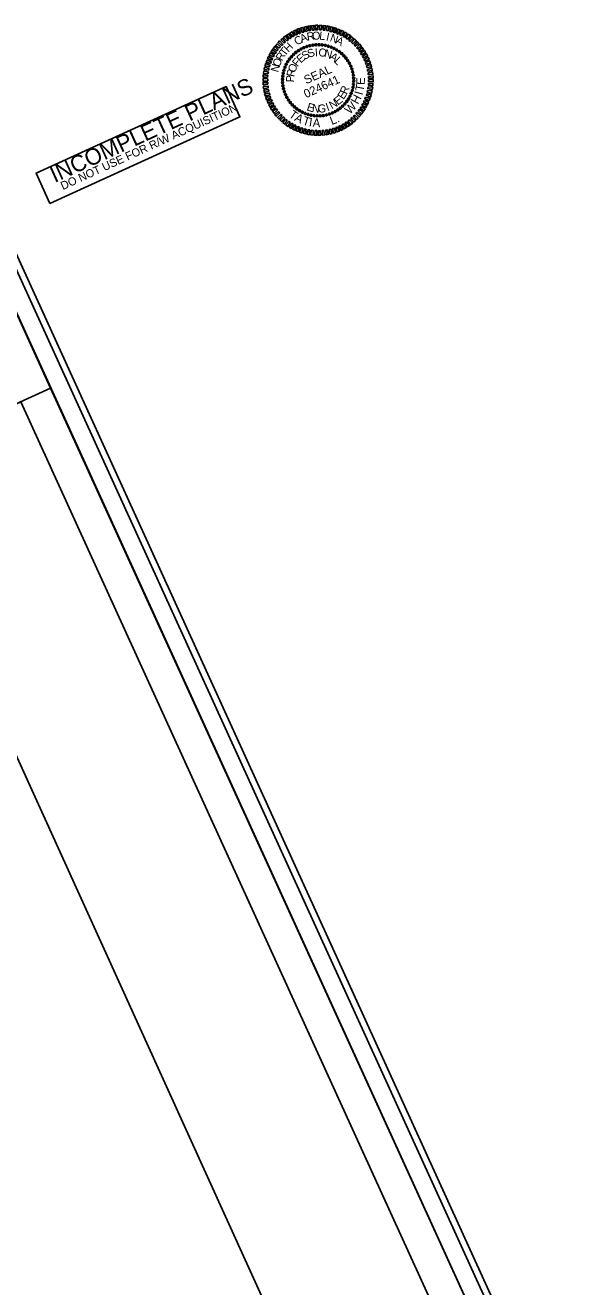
# Model space of a CAD drawing. Extents: x 2247910 to 2249896, y 662531 to 664261.
# Drawn here: x 2249505 to 2249896, y 663373 to 664261 of the extents above; entities that cross this region are included whole.
import ezdxf

# ---------------------------------------------------------------- set-up
doc = ezdxf.new("R2010")
doc.units = 0
for name, color, linetype in [('Sheet Clip Boundary CELL', 7, 'Continuous'), ('Sheet Layout Plan Border', 7, 'Continuous'), ('Sheet Plan CELL', 7, 'Continuous'), ('Sheet Plan Layout CELL', 7, 'Continuous'), ('Sheet Plot Border Inside CELL', 7, 'Continuous'), ('Sheet Plot Border Outside CELL', 7, 'Continuous'), ('Sheet Professional Seal CELL', 7, 'Continuous'), ('Sheet Sticker Incomplete CELL', 7, 'Continuous')]:
    doc.layers.add(name, color=color, linetype=linetype)

msp = doc.modelspace()

# ---------------------------------------------------------------- linework, layer by layer
at = {"layer": 'Sheet Clip Boundary CELL'}
msp.add_lwpolyline([(2248241.67, 663371.06), (2248514.44, 662770.57), (2248551.22, 662641.58), (2249825.2, 663222.11), (2249780.68, 663312.06), (2249743.43, 663294.89), (2249677.44, 663353.62), (2249425.27, 663908.72), (2249477.5, 663985.14), (2249305.27, 663906.66), (2249217.58, 664099.11), (2248115.83, 663597.06)], close=True, dxfattribs=at)
at = {"layer": 'Sheet Layout Plan Border'}
msp.add_lwpolyline([(2248198.13, 663481.51), (2248575.77, 662652.77), (2249849.75, 663233.3), (2249502.05, 663996.33), (2249329.83, 663917.85), (2249242.13, 664110.3), (2248140.38, 663608.25)], close=True, dxfattribs=at)
at = {"layer": 'Sheet Plan CELL'}
for points in [[(2249435.32, 664198.33), (2248070.33, 663576.33), (2248505.72, 662620.85), (2249870.7, 663242.85)], [(2248505.72, 662620.85), (2248070.31, 663576.29), (2249253.26, 664115.38), (2249268.84, 664081.19), (2249359.88, 664122.68), (2249406.53, 664020.29), (2249497.53, 664061.77), (2249870.7, 663242.85)]]:
    msp.add_lwpolyline(points, close=True, dxfattribs=at)
at = {"layer": 'Sheet Plan Layout CELL'}
for points in [[(2249305.27, 663906.66), (2249523.01, 664005.88), (2249435.34, 664198.34), (2249217.58, 664099.11)], [(2248070.31, 663576.29), (2248505.72, 662620.85), (2249870.68, 663242.84), (2249522.99, 664005.87), (2249305.27, 663906.66), (2249217.58, 664099.11)]]:
    msp.add_lwpolyline(points, close=True, dxfattribs=at)
at = {"layer": 'Sheet Plot Border Inside CELL'}
msp.add_lwpolyline([(2248367.09, 662554.92), (2249883.1, 663245.75), (2249445.65, 664205.77), (2247929.62, 663514.94)], close=True, dxfattribs=at)
at = {"layer": 'Sheet Plot Border Outside CELL'}
msp.add_lwpolyline([(2248363.56, 662531.33), (2249895.5, 663229.41), (2249441.45, 664225.83), (2247909.5, 663527.75)], close=True, dxfattribs=at)
at = {"layer": 'Sheet Professional Seal CELL'}
for p, q in [((2249705.47, 664247.08), (2249705.47, 664247.08)), ((2249707.57, 664247.54), (2249707.57, 664247.54)), ((2249709.77, 664247.78), (2249709.77, 664247.78)), ((2249711.97, 664247.79), (2249711.97, 664247.79)), ((2249714.16, 664247.69), (2249714.16, 664247.69)), ((2249716.31, 664247.29), (2249716.31, 664247.29)), ((2249692.51, 664239.35), (2249692.51, 664239.35)), ((2249694, 664240.91), (2249694, 664240.91)), ((2249695.66, 664242.33), (2249695.66, 664242.33)), ((2249697.5, 664243.61), (2249697.5, 664243.61)), ((2249699.33, 664244.77), (2249699.33, 664244.77)), ((2249701.31, 664245.73), (2249701.31, 664245.73)), ((2249703.37, 664246.51), (2249703.37, 664246.51)), ((2249718.46, 664246.79), (2249718.46, 664246.79)), ((2249720.5, 664246.07), (2249720.5, 664246.07)), ((2249722.55, 664245.19), (2249722.55, 664245.19)), ((2249724.41, 664244.12), (2249724.41, 664244.12)), ((2249726.24, 664242.87), (2249726.24, 664242.87)), ((2249727.96, 664241.51), (2249727.96, 664241.51)), ((2249729.52, 664240.02), (2249729.52, 664240.02)), ((2249730.94, 664238.36), (2249730.94, 664238.36)), ((2249687.23, 664229.86), (2249687.23, 664229.86)), ((2249687.95, 664231.89), (2249687.95, 664231.89)), ((2249688.83, 664233.94), (2249688.83, 664233.94)), ((2249689.9, 664235.8), (2249689.9, 664235.8)), ((2249691.15, 664237.64), (2249691.15, 664237.64)), ((2249732.21, 664236.52), (2249732.21, 664236.52)), ((2249733.38, 664234.69), (2249733.38, 664234.69)), ((2249734.34, 664232.71), (2249734.34, 664232.71)), ((2249735.11, 664230.64), (2249735.11, 664230.64)), ((2249686.23, 664223.36), (2249686.23, 664223.36)), ((2249686.24, 664221.16), (2249686.24, 664221.16)), ((2249686.33, 664225.55), (2249686.33, 664225.55)), ((2249686.72, 664227.7), (2249686.72, 664227.7)), ((2249711.31, 664222.7), (2249711.31, 664222.7)), ((2249735.69, 664228.54), (2249735.69, 664228.54)), ((2249736.15, 664226.45), (2249736.15, 664226.45)), ((2249736.38, 664224.24), (2249736.38, 664224.24)), ((2249736.39, 664222.05), (2249736.39, 664222.05)), ((2249686.48, 664218.96), (2249686.48, 664218.96)), ((2249686.94, 664216.87), (2249686.94, 664216.87)), ((2249687.51, 664214.76), (2249687.51, 664214.76)), ((2249688.29, 664212.7), (2249688.29, 664212.7)), ((2249733.8, 664211.47), (2249733.8, 664211.47)), ((2249734.68, 664213.52), (2249734.68, 664213.52)), ((2249735.4, 664215.55), (2249735.4, 664215.55)), ((2249735.9, 664217.71), (2249735.9, 664217.71)), ((2249736.29, 664219.86), (2249736.29, 664219.86)), ((2249689.25, 664210.72), (2249689.25, 664210.72)), ((2249690.41, 664208.89), (2249690.41, 664208.89)), ((2249691.69, 664207.05), (2249691.69, 664207.05)), ((2249693.11, 664205.39), (2249693.11, 664205.39)), ((2249694.66, 664203.9), (2249694.66, 664203.9)), ((2249726.97, 664203.08), (2249726.97, 664203.08)), ((2249728.63, 664204.5), (2249728.63, 664204.5)), ((2249730.12, 664206.05), (2249730.12, 664206.05)), ((2249731.48, 664207.77), (2249731.48, 664207.77)), ((2249732.73, 664209.61), (2249732.73, 664209.61)), ((2249696.38, 664202.54), (2249696.38, 664202.54)), ((2249698.22, 664201.29), (2249698.22, 664201.29)), ((2249700.08, 664200.22), (2249700.08, 664200.22)), ((2249702.13, 664199.34), (2249702.13, 664199.34)), ((2249704.16, 664198.62), (2249704.16, 664198.62)), ((2249706.31, 664198.11), (2249706.31, 664198.11)), ((2249708.47, 664197.72), (2249708.47, 664197.72)), ((2249710.66, 664197.62), (2249710.66, 664197.62)), ((2249712.85, 664197.63), (2249712.85, 664197.63)), ((2249715.05, 664197.87), (2249715.05, 664197.87)), ((2249717.15, 664198.33), (2249717.15, 664198.33)), ((2249719.25, 664198.9), (2249719.25, 664198.9)), ((2249721.32, 664199.68), (2249721.32, 664199.68)), ((2249723.3, 664200.64), (2249723.3, 664200.64)), ((2249725.13, 664201.8), (2249725.13, 664201.8))]:
    msp.add_line(p, q, dxfattribs=at)
for points in [[(2249693.3, 664253.29), (2249691.47, 664255.97), (2249692.94, 664256.86), (2249694.33, 664253.92)], [(2249695.47, 664254.55), (2249693.9, 664257.41), (2249695.42, 664258.05), (2249696.58, 664255.01)], [(2249697.68, 664255.5), (2249696.33, 664258.46), (2249697.85, 664259.1), (2249698.79, 664255.96)], [(2249700.01, 664256.4), (2249698.85, 664259.44), (2249700.47, 664259.86), (2249701.19, 664256.72)], [(2249702.36, 664257.04), (2249701.45, 664260.13), (2249703.05, 664260.59), (2249703.52, 664257.4)], [(2249704.91, 664257.59), (2249704.02, 664260.76), (2249705.73, 664261.1), (2249705.97, 664257.8)], [(2249707.36, 664258), (2249706.76, 664261.13), (2249708.38, 664261.32), (2249708.47, 664258.11)], [(2249709.79, 664258.11), (2249709.53, 664261.46), (2249711.05, 664261.49), (2249710.98, 664258.27)], [(2249712.23, 664258.18), (2249712.14, 664261.38), (2249713.84, 664261.39), (2249713.46, 664258.14)], [(2249714.8, 664258.09), (2249714.84, 664261.24), (2249716.56, 664261.09), (2249715.91, 664257.94)], [(2249717.13, 664257.67), (2249717.52, 664261.03), (2249719.14, 664260.62), (2249718.38, 664257.58)], [(2249719.62, 664257.16), (2249720.16, 664260.43), (2249721.8, 664259.96), (2249720.77, 664256.91)], [(2249721.99, 664256.53), (2249722.78, 664259.75), (2249724.37, 664259.16), (2249723.17, 664256.25)], [(2249724.35, 664255.69), (2249725.34, 664258.72), (2249726.93, 664258.12), (2249725.37, 664255.27)], [(2249726.69, 664254.78), (2249727.85, 664257.78), (2249729.37, 664256.98), (2249727.75, 664254.16)], [(2249728.87, 664253.62), (2249730.23, 664256.55), (2249731.69, 664255.63), (2249729.81, 664253.01)], [(2249683.91, 664245.32), (2249681.29, 664247.21), (2249682.41, 664248.49), (2249684.72, 664246.19)], [(2249685.48, 664247.19), (2249683.09, 664249.29), (2249684.21, 664250.46), (2249686.49, 664247.98)], [(2249687.37, 664248.94), (2249685.08, 664251.19), (2249686.31, 664252.24), (2249688.18, 664249.69)], [(2249689.29, 664250.52), (2249687.02, 664252.95), (2249688.43, 664253.98), (2249690.14, 664251.19)], [(2249691.24, 664252.02), (2249689.19, 664254.6), (2249690.63, 664255.42), (2249692.27, 664252.65)], [(2249730.9, 664252.3), (2249732.52, 664255.13), (2249734.01, 664254.16), (2249731.95, 664251.68)], [(2249733, 664250.84), (2249734.82, 664253.59), (2249736.05, 664252.45), (2249733.94, 664250.22)], [(2249734.8, 664249.29), (2249736.86, 664251.88), (2249738.12, 664250.7), (2249735.71, 664248.5)], [(2249736.59, 664247.53), (2249738.83, 664249.98), (2249739.97, 664248.8), (2249737.48, 664246.78)], [(2249738.32, 664245.68), (2249740.75, 664248.05), (2249741.71, 664246.68), (2249739.07, 664244.87)], [(2249678.68, 664236.9), (2249675.77, 664237.99), (2249676.36, 664239.58), (2249679.26, 664237.93)], [(2249679.86, 664239.14), (2249676.91, 664240.43), (2249677.7, 664241.94), (2249680.46, 664240.12)], [(2249680.97, 664241.29), (2249678.23, 664242.84), (2249679.02, 664244.25), (2249681.72, 664242.29)], [(2249682.45, 664243.34), (2249679.65, 664245.03), (2249680.73, 664246.4), (2249683.07, 664244.28)], [(2249739.86, 664243.74), (2249742.33, 664245.91), (2249743.31, 664244.49), (2249740.57, 664242.91)], [(2249741.26, 664241.75), (2249743.93, 664243.73), (2249744.77, 664242.25), (2249741.94, 664240.74)], [(2249742.53, 664239.69), (2249745.32, 664241.4), (2249746.12, 664239.89), (2249743.12, 664238.64)], [(2249743.61, 664237.43), (2249746.51, 664238.92), (2249747.21, 664237.37), (2249744.11, 664236.34)], [(2249675.99, 664227.37), (2249672.82, 664227.57), (2249673.15, 664229.26), (2249676.35, 664228.52)], [(2249676.53, 664229.81), (2249673.37, 664230.24), (2249673.63, 664231.95), (2249676.73, 664230.95)], [(2249677.11, 664232.16), (2249673.93, 664232.86), (2249674.39, 664234.5), (2249677.37, 664233.27)], [(2249677.91, 664234.62), (2249674.74, 664235.43), (2249675.4, 664236.99), (2249678.31, 664235.68)], [(2249744.61, 664235.14), (2249747.6, 664236.4), (2249748.2, 664234.85), (2249745.01, 664234)], [(2249745.37, 664232.85), (2249748.41, 664233.9), (2249748.93, 664232.28), (2249745.64, 664231.65)], [(2249746.07, 664230.36), (2249749.05, 664231.29), (2249749.44, 664229.59), (2249746.14, 664229.24)], [(2249675.84, 664222.41), (2249672.54, 664222.17), (2249672.58, 664223.89), (2249675.84, 664223.62)], [(2249675.84, 664219.99), (2249672.65, 664219.53), (2249672.6, 664221.21), (2249675.91, 664221.18)], [(2249675.79, 664224.92), (2249672.68, 664224.87), (2249672.72, 664226.59), (2249675.95, 664226.03)], [(2249746.47, 664227.91), (2249749.56, 664228.61), (2249749.93, 664226.96), (2249746.54, 664226.79)], [(2249746.83, 664220.49), (2249749.94, 664220.54), (2249749.91, 664218.82), (2249746.68, 664219.38)], [(2249746.79, 664225.42), (2249749.98, 664225.88), (2249750.03, 664224.2), (2249746.72, 664224.23)], [(2249746.79, 664223), (2249750.09, 664223.24), (2249750.05, 664221.52), (2249746.79, 664221.79)], [(2249676.15, 664217.5), (2249673.06, 664216.8), (2249672.7, 664218.45), (2249676.08, 664218.62)], [(2249676.56, 664215.05), (2249673.57, 664214.12), (2249673.19, 664215.81), (2249676.49, 664216.17)], [(2249677.25, 664212.56), (2249674.22, 664211.5), (2249673.69, 664213.13), (2249676.98, 664213.75)], [(2249745.52, 664213.24), (2249748.7, 664212.55), (2249748.23, 664210.91), (2249745.26, 664212.14)], [(2249746.1, 664215.6), (2249749.26, 664215.17), (2249749, 664213.46), (2249745.9, 664214.46)], [(2249746.63, 664218.04), (2249749.8, 664217.83), (2249749.47, 664216.15), (2249746.28, 664216.89)], [(2249678.02, 664210.27), (2249675.02, 664209.01), (2249674.43, 664210.56), (2249677.61, 664211.4)], [(2249679.01, 664207.98), (2249676.12, 664206.49), (2249675.41, 664208.04), (2249678.51, 664209.07)], [(2249680.1, 664205.72), (2249677.3, 664204.01), (2249676.51, 664205.52), (2249679.51, 664206.77)], [(2249681.36, 664203.66), (2249678.7, 664201.68), (2249677.86, 664203.16), (2249680.68, 664204.67)], [(2249741.66, 664204.12), (2249744.4, 664202.57), (2249743.61, 664201.16), (2249740.91, 664203.12)], [(2249742.77, 664206.27), (2249745.72, 664204.98), (2249744.92, 664203.47), (2249742.17, 664205.29)], [(2249743.94, 664208.51), (2249746.86, 664207.42), (2249746.26, 664205.83), (2249743.37, 664207.48)], [(2249744.72, 664210.79), (2249747.89, 664209.98), (2249747.23, 664208.42), (2249744.32, 664209.73)], [(2249682.77, 664201.67), (2249680.3, 664199.49), (2249679.32, 664200.92), (2249682.06, 664202.5)], [(2249684.31, 664199.73), (2249681.88, 664197.36), (2249680.92, 664198.73), (2249683.56, 664200.54)], [(2249686.03, 664197.88), (2249683.8, 664195.43), (2249682.66, 664196.61), (2249685.14, 664198.63)], [(2249687.83, 664196.11), (2249685.77, 664193.53), (2249684.51, 664194.71), (2249686.92, 664196.91)], [(2249689.63, 664194.57), (2249687.81, 664191.82), (2249686.57, 664192.96), (2249688.69, 664195.19)], [(2249691.73, 664193.11), (2249690.1, 664190.28), (2249688.62, 664191.25), (2249690.67, 664193.73)], [(2249733.34, 664194.89), (2249735.6, 664192.46), (2249734.2, 664191.43), (2249732.49, 664194.22)], [(2249735.25, 664196.47), (2249737.55, 664194.22), (2249736.32, 664193.17), (2249734.44, 664195.72)], [(2249737.15, 664198.22), (2249739.54, 664196.12), (2249738.42, 664194.95), (2249736.14, 664197.43)], [(2249738.72, 664200.09), (2249741.34, 664198.2), (2249740.22, 664196.92), (2249737.9, 664199.22)], [(2249740.18, 664202.07), (2249742.98, 664200.38), (2249741.9, 664199.01), (2249739.56, 664201.13)], [(2249693.76, 664191.78), (2249692.4, 664188.86), (2249690.94, 664189.78), (2249692.82, 664192.4)], [(2249695.93, 664190.63), (2249694.77, 664187.63), (2249693.26, 664188.42), (2249694.88, 664191.25)], [(2249698.27, 664189.72), (2249697.29, 664186.69), (2249695.7, 664187.29), (2249697.26, 664190.14)], [(2249700.64, 664188.88), (2249699.85, 664185.66), (2249698.26, 664186.25), (2249699.46, 664189.16)], [(2249703.01, 664188.25), (2249702.47, 664184.98), (2249700.83, 664185.45), (2249701.85, 664188.5)], [(2249705.5, 664187.74), (2249705.11, 664184.37), (2249703.49, 664184.79), (2249704.25, 664187.83)], [(2249707.83, 664187.32), (2249707.78, 664184.17), (2249706.07, 664184.32), (2249706.72, 664187.47)], [(2249710.4, 664187.23), (2249710.49, 664184.03), (2249708.79, 664184.02), (2249709.17, 664187.27)], [(2249712.84, 664187.3), (2249713.1, 664183.95), (2249711.58, 664183.92), (2249711.65, 664187.14)], [(2249715.26, 664187.41), (2249715.87, 664184.28), (2249714.25, 664184.09), (2249714.16, 664187.29)], [(2249717.72, 664187.82), (2249718.61, 664184.65), (2249716.9, 664184.31), (2249716.66, 664187.61)], [(2249720.26, 664188.37), (2249721.18, 664185.28), (2249719.58, 664184.82), (2249719.11, 664188.01)], [(2249722.61, 664189.01), (2249723.78, 664185.97), (2249722.15, 664185.55), (2249721.44, 664188.69)], [(2249724.95, 664189.91), (2249726.3, 664186.95), (2249724.78, 664186.31), (2249723.84, 664189.45)], [(2249727.15, 664190.86), (2249728.73, 664188), (2249727.21, 664187.36), (2249726.04, 664190.4)], [(2249729.33, 664192.12), (2249731.15, 664189.44), (2249729.69, 664188.55), (2249728.3, 664191.49)], [(2249731.38, 664193.39), (2249733.44, 664190.81), (2249732, 664189.99), (2249730.36, 664192.76)]]:
    msp.add_lwpolyline(points, close=True, dxfattribs=at)
for centre, major_axis in [((2249703.35, 664246.49), (-0.229, 0.683)), ((2249705.45, 664247.09), (-0.168, 0.7)), ((2249707.6, 664247.51), (-0.107, 0.712)), ((2249709.78, 664247.74), (-0.044, 0.719)), ((2249711.96, 664247.78), (0.019, 0.72)), ((2249714.15, 664247.62), (0.081, 0.715)), ((2249716.31, 664247.28), (0.143, 0.706)), ((2249718.43, 664246.75), (0.204, 0.69)), ((2249691.15, 664237.62), (-0.579, 0.428)), ((2249692.53, 664239.32), (-0.539, 0.477)), ((2249694.05, 664240.89), (-0.496, 0.522)), ((2249695.7, 664242.33), (-0.448, 0.563)), ((2249697.47, 664243.62), (-0.398, 0.6)), ((2249699.34, 664244.74), (-0.344, 0.633)), ((2249701.31, 664245.7), (-0.287, 0.66)), ((2249720.5, 664246.04), (0.264, 0.67)), ((2249722.5, 664245.15), (0.321, 0.644)), ((2249724.41, 664244.09), (0.376, 0.614)), ((2249726.23, 664242.87), (0.428, 0.579)), ((2249727.93, 664241.49), (0.477, 0.539)), ((2249729.5, 664239.97), (0.522, 0.496)), ((2249730.94, 664238.32), (0.563, 0.448)), ((2249687.26, 664229.82), (-0.69, 0.204)), ((2249687.98, 664231.89), (-0.67, 0.264)), ((2249688.87, 664233.89), (-0.644, 0.321)), ((2249689.93, 664235.8), (-0.614, 0.376)), ((2249732.22, 664236.55), (0.6, 0.398)), ((2249733.35, 664234.68), (0.633, 0.344)), ((2249734.31, 664232.71), (0.66, 0.287)), ((2249735.1, 664230.67), (0.683, 0.229)), ((2249735.7, 664228.56), (0.7, 0.168)), ((2249686.24, 664223.36), (-0.72, 0.019)), ((2249686.28, 664221.17), (-0.719, -0.044)), ((2249686.39, 664225.54), (-0.715, 0.081)), ((2249686.74, 664227.7), (-0.706, 0.143)), ((2249736.12, 664226.42), (0.712, 0.107)), ((2249736.23, 664219.87), (0.715, -0.081)), ((2249736.35, 664224.24), (0.719, 0.044)), ((2249736.38, 664222.05), (0.72, -0.019)), ((2249686.51, 664218.99), (-0.712, -0.107)), ((2249686.93, 664216.84), (-0.7, -0.168)), ((2249687.53, 664214.74), (-0.683, -0.229)), ((2249688.32, 664212.7), (-0.66, -0.287)), ((2249689.28, 664210.73), (-0.633, -0.344)), ((2249733.76, 664211.52), (0.644, -0.321)), ((2249734.65, 664213.52), (0.67, -0.264)), ((2249735.36, 664215.59), (0.69, -0.204)), ((2249735.89, 664217.71), (0.706, -0.143)), ((2249690.4, 664208.86), (-0.6, -0.398)), ((2249691.69, 664207.09), (-0.563, -0.448)), ((2249693.12, 664205.44), (-0.522, -0.496)), ((2249694.7, 664203.92), (-0.477, -0.539)), ((2249696.4, 664202.54), (-0.428, -0.579)), ((2249725.16, 664201.79), (0.398, -0.6)), ((2249726.93, 664203.08), (0.448, -0.563)), ((2249728.58, 664204.52), (0.496, -0.522)), ((2249730.1, 664206.09), (0.539, -0.477)), ((2249731.48, 664207.79), (0.579, -0.428)), ((2249732.7, 664209.6), (0.614, -0.376)), ((2249698.21, 664201.32), (-0.376, -0.614)), ((2249700.13, 664200.26), (-0.321, -0.644)), ((2249702.13, 664199.37), (-0.264, -0.67)), ((2249704.2, 664198.66), (-0.204, -0.69)), ((2249706.32, 664198.13), (-0.143, -0.706)), ((2249708.48, 664197.79), (-0.081, -0.715)), ((2249710.66, 664197.63), (-0.019, -0.72)), ((2249712.85, 664197.67), (0.044, -0.719)), ((2249715.03, 664197.9), (0.107, -0.712)), ((2249717.17, 664198.32), (0.168, -0.7)), ((2249719.28, 664198.92), (0.229, -0.683)), ((2249721.32, 664199.71), (0.287, -0.66)), ((2249723.29, 664200.67), (0.344, -0.633))]:
    msp.add_ellipse(centre, major_axis=major_axis, ratio=0.999708, dxfattribs=at)
at = {"layer": 'Sheet Sticker Incomplete CELL'}
msp.add_lwpolyline([(2249522.51, 664135.97), (2249512.77, 664157.36), (2249646.53, 664218.31), (2249656.28, 664196.93)], close=True, dxfattribs=at)

# ---------------------------------------------------------------- texts
at = {"layer": 'Sheet Professional Seal CELL'}
for s, height, rotation, p in [('R', 5.64, 9.13336, (2249703.79, 664250.54)), ('O', 5.64, 1.93343, (2249707.15, 664251.25)), ('L', 5.64, 354.73314, (2249711.92, 664251.39)), ('I', 5.64, 347.5324, (2249716.6, 664250.89)), ('H', 5.64, 45.13174, (2249690.33, 664242.1)), ('C', 5.64, 30.73213, (2249696.41, 664247.07)), ('A', 5.64, 23.53258, (2249699.88, 664248.98)), ('N', 5.64, 340.33117, (2249719.2, 664250.37)), ('A', 5.64, 333.12941, (2249723.1, 664248.91)), ('O', 5.64, 66.734, (2249684.02, 664231.58)), ('R', 5.64, 59.53277, (2249685.87, 664235.83)), ('T', 5.64, 52.33203, (2249688.05, 664239.25)), ('F', 5.64, 50.47929, (2249696.78, 664231.8)), ('E', 5.64, 41.12333, (2249699.07, 664234.49)), ('S', 5.64, 31.76787, (2249701.77, 664236.87)), ('S', 5.64, 22.41266, (2249705.03, 664238.41)), ('I', 5.64, 3.70186, (2249709.23, 664239.56)), ('O', 5.64, 354.34574, (2249711.34, 664239.75)), ('N', 5.64, 344.98887, (2249715.22, 664239.32)), ('A', 5.64, 326.27253, (2249718.89, 664238.14)), ('L', 5.64, 316.91311, (2249722.1, 664235.81)), ('N', 5.64, 73.93576, (2249683.13, 664227.99)), ('R', 5.64, 78.55191, (2249694.43, 664224.79)), ('O', 5.64, 69.1935, (2249695, 664227.74)), ('SEAL', 5.998, 24.51226, (2249702.96, 664219.83)), ('P', 5.64, 87.91115, (2249694.3, 664221.21)), ('024641', 5.998, 24.51226, (2249702.83, 664210.04)), ('E', 6, 87.63115, (2249744.09, 664219.35)), ('E', 5.64, 38.92402, (2249725.24, 664204.82)), ('E', 5.64, 57.63635, (2249729.25, 664208.79)), ('R', 5.64, 66.99367, (2249731.51, 664212.4)), ('H', 6, 61.83328, (2249739.36, 664205.42)), ('I', 6, 74.34486, (2249742.44, 664211.9)), ('T', 6, 79.10933, (2249743.23, 664214.53)), ('E', 5.64, 342.78915, (2249702.88, 664201.66)), ('N', 5.64, 352.14622, (2249706.73, 664200.45)), ('G', 5.64, 1.5025, (2249711.13, 664199.98)), ('I', 5.64, 20.21346, (2249717.87, 664200.97)), ('N', 5.64, 29.56865, (2249720.98, 664202.22)), ('W', 6, 46.12601, (2249733.64, 664198.47)), ('T', 6, 323.6774, (2249690.22, 664197.39)), ('A', 6, 332.19922, (2249694.2, 664194.54)), ('T', 6, 343.27759, (2249699.93, 664191.78)), ('I', 6, 351.79941, (2249704.64, 664190.44)), ('A', 6, 356.56388, (2249707.35, 664189.99)), ('L', 6, 20.42498, (2249720.92, 664191.18)), ('.', 6, 28.28829, (2249725.14, 664192.79))]:
    msp.add_text(s, height=height, rotation=rotation, dxfattribs=at).set_placement(p)
at = {"layer": 'Sheet Sticker Incomplete CELL'}
for s, height, p in [('INCOMPLETE PLANS', 11.52, (2249525.8, 664150.33)), ('DO NOT USE FOR R/W ACQUISITION', 5.76, (2249531.64, 664145.35))]:
    msp.add_text(s, height=height, rotation=24.49794, dxfattribs=at).set_placement(p)

doc.saveas('drawing.dxf')
